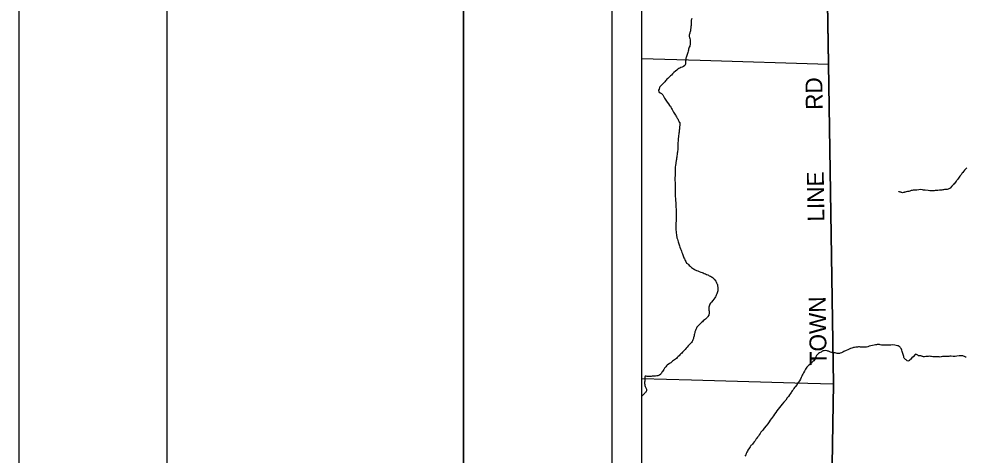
# Model space of a CAD drawing. Extents: x 0 to 34, y 0 to 22.
# Drawn here: x 0 to 3.195, y 15.642 to 17.112 of the extents above; entities that cross this region are included whole.
import ezdxf

# ---------------------------------------------------------------- set-up
doc = ezdxf.new("R2010")
doc.units = 0
for name, color, linetype in [('GM_X_Corporation', 7, 'Continuous'), ('GM_X_Minor_River', 7, 'Continuous'), ('GM_X_Township_Road', 7, 'Continuous'), ('GM_X_Township_Road_Text', 7, 'Continuous'), ('SH_Border', 7, 'Continuous'), ('SH_Cut_Line', 7, 'Continuous'), ('SH_Data', 7, 'Continuous')]:
    doc.layers.add(name, color=color, linetype=linetype)

msp = doc.modelspace()

# ---------------------------------------------------------------- linework, layer by layer
at = {"layer": 'GM_X_Corporation'}
for points in [[(3.1996, 20.2345), (3.1561, 20.2337), (3.1064, 20.2336), (3.0286, 20.2331), (3.0007, 20.2328), (2.9354, 20.2326), (2.8825, 20.2322), (2.8234, 20.2319), (2.7333, 20.2317), (2.6825, 20.2316), (2.6344, 20.2324), (2.5847, 20.2334), (2.535, 20.2346), (2.5164, 20.2351), (2.4604, 20.2364), (2.3921, 20.2383), (2.333, 20.2398), (2.2833, 20.2411), (2.246, 20.2419), (2.187, 20.2434), (2.1124, 20.2453), (2.1, 20.2456), (2.1, 14.1)], [(3.1996, 20.2345), (3.1561, 20.2337), (3.1064, 20.2336), (3.0286, 20.2331), (3.0007, 20.2328), (2.9354, 20.2326), (2.8825, 20.2322), (2.8234, 20.2319), (2.7333, 20.2317), (2.6825, 20.2316), (2.6883, 19.5017), (2.7024, 18.7188), (2.7184, 17.7156), (2.7304, 16.9599), (2.7477, 15.8824), (2.7366, 15.2014)]]:
    msp.add_lwpolyline(points, dxfattribs=at)
msp.add_lwpolyline([(2.1, 20.2456), (2.1, 15.2121), (2.7366, 15.2014), (2.7477, 15.8824), (2.7304, 16.9599), (2.7184, 17.7156), (2.7024, 18.7188), (2.6883, 19.5017), (2.6825, 20.2316), (2.6344, 20.2324), (2.5847, 20.2334), (2.535, 20.2346), (2.5164, 20.2351), (2.4604, 20.2364), (2.3921, 20.2383), (2.333, 20.2398), (2.2833, 20.2411), (2.246, 20.2419), (2.187, 20.2434), (2.1124, 20.2453)], close=True, dxfattribs=at)
at = {"layer": 'GM_X_Minor_River'}
for points in [[(2.2695, 17.1126), (2.2684, 17.1103), (2.268, 17.108), (2.2675, 17.1046), (2.2671, 17.1005), (2.2671, 17.0978), (2.2671, 17.0959), (2.267, 17.0929), (2.267, 17.0894), (2.2666, 17.0864), (2.2665, 17.0841)], [(2.2665, 17.0841), (2.2665, 17.0822), (2.2661, 17.0799), (2.2657, 17.0773), (2.2653, 17.0746), (2.2649, 17.0716), (2.2637, 17.0682), (2.2629, 17.0663), (2.2625, 17.0636), (2.2617, 17.0606), (2.2609, 17.058), (2.2609, 17.0553), (2.2612, 17.0526), (2.2616, 17.0507), (2.2623, 17.0488), (2.2634, 17.0454), (2.2641, 17.0416), (2.2644, 17.034), (2.2644, 17.0313), (2.264, 17.0271), (2.2639, 17.0245), (2.2631, 17.0218), (2.2627, 17.0199), (2.2612, 17.0161), (2.26, 17.0131), (2.2588, 17.0093), (2.258, 17.007), (2.2572, 17.0029), (2.256, 16.9987), (2.2552, 16.9949), (2.254, 16.9915), (2.2532, 16.9885), (2.252, 16.9851), (2.2509, 16.982), (2.2501, 16.9798), (2.2497, 16.9767), (2.2492, 16.9729), (2.2488, 16.9695), (2.2484, 16.9657), (2.2484, 16.9634), (2.2483, 16.9615), (2.2479, 16.9589), (2.2467, 16.9551), (2.2421, 16.9514), (2.2368, 16.9491), (2.233, 16.9477), (2.2295, 16.9462), (2.2261, 16.9447), (2.2226, 16.9425), (2.2196, 16.9391), (2.215, 16.9361), (2.2088, 16.9308), (2.2065, 16.9286), (2.2046, 16.9267), (2.2007, 16.9226), (2.198, 16.9203), (2.1892, 16.9113), (2.1854, 16.9083), (2.1834, 16.9057), (2.1807, 16.9027), (2.1784, 16.8997), (2.1761, 16.8978), (2.1742, 16.8951), (2.1719, 16.8925), (2.1688, 16.8891), (2.1657, 16.8861), (2.163, 16.8842), (2.1615, 16.8824), (2.1607, 16.8805), (2.1595, 16.8755), (2.1579, 16.8718), (2.159, 16.8664), (2.1631, 16.863), (2.1669, 16.8606), (2.1692, 16.8587), (2.1714, 16.8556), (2.1744, 16.851), (2.1778, 16.8449), (2.1822, 16.8384), (2.1863, 16.8315), (2.1908, 16.8254), (2.1946, 16.82), (2.1976, 16.8173), (2.1991, 16.8143), (2.2013, 16.8104), (2.2031, 16.8062), (2.2057, 16.8016), (2.208, 16.7978), (2.2098, 16.7944), (2.2121, 16.7905), (2.2143, 16.7875), (2.2158, 16.7848), (2.218, 16.7813), (2.2203, 16.7771), (2.2221, 16.7745), (2.2236, 16.7718), (2.2259, 16.7672), (2.2273, 16.7641), (2.2288, 16.7622), (2.2291, 16.7538), (2.2287, 16.7481)], [(2.2287, 16.7481), (2.2283, 16.7447), (2.2278, 16.7406), (2.2274, 16.7371), (2.227, 16.7341), (2.2266, 16.7299), (2.2261, 16.7265), (2.2257, 16.7231), (2.2253, 16.7185), (2.2245, 16.714), (2.224, 16.709), (2.2236, 16.7045), (2.2232, 16.6999), (2.2231, 16.6958), (2.2231, 16.692), (2.2226, 16.687), (2.2226, 16.6821), (2.2225, 16.6779), (2.2221, 16.6741), (2.222, 16.6707), (2.2216, 16.6665), (2.2212, 16.6631), (2.2208, 16.6589), (2.2199, 16.6547), (2.2195, 16.6509), (2.2187, 16.6464), (2.2179, 16.6426), (2.2175, 16.6384), (2.2167, 16.6342), (2.2146, 16.6175), (2.2141, 16.6138), (2.2137, 16.6096), (2.2133, 16.6046), (2.2132, 16.5986), (2.2135, 16.5932), (2.2134, 16.5879), (2.2134, 16.5826), (2.2129, 16.5777), (2.2129, 16.5723), (2.2128, 16.567), (2.2131, 16.5605), (2.2134, 16.5533), (2.2134, 16.5488), (2.2137, 16.5446), (2.2136, 16.54), (2.2136, 16.5358), (2.2135, 16.5309), (2.2135, 16.5267), (2.2138, 16.5229), (2.2138, 16.5191), (2.2141, 16.5134), (2.2144, 16.5069), (2.2147, 16.4986), (2.2154, 16.4936), (2.2157, 16.4887), (2.216, 16.4826), (2.2163, 16.4769), (2.2166, 16.4712), (2.2169, 16.4655), (2.2169, 16.4609), (2.2168, 16.456), (2.2167, 16.4514), (2.2167, 16.4468), (2.2166, 16.4415), (2.2166, 16.4351), (2.2165, 16.4297), (2.2161, 16.4248), (2.216, 16.4195), (2.2159, 16.4145), (2.2159, 16.4096), (2.2162, 16.405), (2.2161, 16.4001), (2.2165, 16.3955), (2.2168, 16.3906), (2.2175, 16.3841), (2.2189, 16.3746), (2.2211, 16.3692), (2.2226, 16.3647), (2.2236, 16.3601), (2.228, 16.3475), (2.2295, 16.3425), (2.2317, 16.3372), (2.2336, 16.3322), (2.2351, 16.3292), (2.2361, 16.325), (2.238, 16.3204), (2.2391, 16.317), (2.2406, 16.3131), (2.2417, 16.3101), (2.2431, 16.3066), (2.2446, 16.3032), (2.2457, 16.3005), (2.2468, 16.2979), (2.2491, 16.2948), (2.2521, 16.2891), (2.2558, 16.286), (2.2585, 16.2837), (2.2607, 16.281), (2.2637, 16.2787), (2.2663, 16.2763), (2.269, 16.274)], [(3.1979, 16.6101), (3.1895, 16.6018), (3.186, 16.5977), (3.1837, 16.5947), (3.1821, 16.5928), (3.1802, 16.5898), (3.1783, 16.5875), (3.1767, 16.5852), (3.174, 16.5815), (3.1721, 16.5781), (3.1694, 16.5747), (3.1671, 16.572), (3.1651, 16.5698), (3.1636, 16.5675), (3.1616, 16.5645), (3.1593, 16.5611), (3.1566, 16.5581), (3.1547, 16.5566), (3.152, 16.5536), (3.147, 16.5476), (3.1408, 16.5419), (3.1347, 16.5382), (3.1313, 16.5371), (3.1267, 16.5372), (3.1225, 16.5368), (3.1187, 16.5361), (3.1161, 16.5358), (3.1134, 16.5351), (3.1115, 16.5351), (3.1054, 16.5348), (3.1001, 16.5341), (3.0955, 16.5334), (3.0921, 16.533), (3.0902, 16.533), (3.0871, 16.5323), (3.0833, 16.532), (3.0784, 16.532), (3.0727, 16.5325), (3.0666, 16.5333), (3.0564, 16.5346), (3.0537, 16.5346), (3.0507, 16.535), (3.0484, 16.5358), (3.0427, 16.5366), (3.0351, 16.5356), (3.029, 16.5345), (3.0263, 16.5342), (3.0229, 16.5342), (3.0195, 16.5343), (3.0161, 16.5343), (3.0126, 16.534), (3.0096, 16.5332), (3.0077, 16.5325), (3.005, 16.5318), (3.0019, 16.5307), (2.9978, 16.53), (2.9932, 16.5289), (2.9894, 16.5278), (2.9875, 16.5278), (2.9856, 16.5267), (2.9833, 16.5263), (2.9806, 16.526), (2.9787, 16.5264), (2.9768, 16.5272), (2.9745, 16.528), (2.9727, 16.5284), (2.9708, 16.5288), (2.9681, 16.5296), (2.9681, 16.5296), (2.9681, 16.5299)], [(2.269, 16.274), (2.272, 16.2717), (2.275, 16.2698), (2.2777, 16.2686), (2.2811, 16.2663), (2.2856, 16.2643), (2.2901, 16.2624), (2.295, 16.2604), (2.3, 16.2588), (2.3045, 16.2573), (2.3079, 16.2557), (2.3113, 16.2541), (2.3155, 16.2522), (2.3196, 16.2502), (2.3234, 16.2491), (2.3261, 16.2479), (2.3287, 16.2463), (2.3332, 16.2444), (2.3366, 16.2424), (2.3389, 16.2413), (2.3412, 16.2397), (2.343, 16.237), (2.3453, 16.2347), (2.3505, 16.2282), (2.3513, 16.2263), (2.3528, 16.2225), (2.355, 16.2183), (2.3565, 16.2164), (2.3568, 16.2125), (2.3575, 16.2072), (2.3578, 16.2023), (2.3574, 16.1985), (2.3574, 16.1958), (2.3562, 16.192), (2.3554, 16.1882), (2.3542, 16.1852), (2.3534, 16.1826), (2.3523, 16.1807), (2.3511, 16.1776), (2.3495, 16.175), (2.3472, 16.1716), (2.3441, 16.1675), (2.3403, 16.1629), (2.336, 16.1573), (2.3333, 16.1539), (2.331, 16.1501), (2.329, 16.1471), (2.3282, 16.1437), (2.3274, 16.1399), (2.327, 16.1354), (2.3273, 16.1308), (2.3277, 16.127), (2.328, 16.1236), (2.3284, 16.1217), (2.3267, 16.1137), (2.324, 16.1088), (2.3221, 16.1065), (2.3205, 16.1039), (2.3182, 16.102), (2.3159, 16.0998), (2.3129, 16.0975), (2.3083, 16.0941), (2.3052, 16.0915), (2.3029, 16.0889), (2.3002, 16.0863), (2.2929, 16.0799), (2.2906, 16.0776), (2.2886, 16.0754), (2.2871, 16.0727), (2.2852, 16.0697), (2.2832, 16.0648), (2.2816, 16.0614), (2.2804, 16.0576), (2.2797, 16.0553), (2.2788, 16.0508), (2.278, 16.0474), (2.2772, 16.0436), (2.2764, 16.0405), (2.2757, 16.0379), (2.2749, 16.0345), (2.2741, 16.0322), (2.2733, 16.0299), (2.2721, 16.0273), (2.2705, 16.0243), (2.2686, 16.0216), (2.2667, 16.019), (2.2632, 16.016), (2.2617, 16.0141), (2.2594, 16.0122), (2.2571, 16.0096), (2.2544, 16.0058), (2.2505, 16.0021), (2.2474, 15.9983), (2.2447, 15.9953), (2.2428, 15.9934), (2.2405, 15.9912), (2.2382, 15.9885), (2.2355, 15.9859), (2.2324, 15.9829), (2.2293, 15.9803), (2.2266, 15.9769)], [(2.9777, 15.9957), (2.9762, 16.0007), (2.974, 16.0038), (2.9721, 16.0057), (2.9706, 16.0076), (2.9687, 16.0084), (2.9657, 16.0096), (2.963, 16.0104), (2.9592, 16.0112), (2.9543, 16.0124), (2.9478, 16.0132), (2.9406, 16.0129), (2.9341, 16.0122), (2.9281, 16.0119), (2.9205, 16.0124), (2.9144, 16.0128), (2.9094, 16.0129), (2.9056, 16.0137), (2.9026, 16.0145), (2.9003, 16.0149), (2.8977, 16.0149), (2.8954, 16.0142), (2.8923, 16.0139), (2.8893, 16.0131), (2.8851, 16.012), (2.868, 16.0088), (2.863, 16.007), (2.8584, 16.0059), (2.8542, 16.0052), (2.8485, 16.0053), (2.8428, 16.0057), (2.8383, 16.0061), (2.8356, 16.0062), (2.8337, 16.0062), (2.8318, 16.0062), (2.8288, 16.0059), (2.8261, 16.0055), (2.8231, 16.0056), (2.8189, 16.0049), (2.8151, 16.0045), (2.8128, 16.0038), (2.8093, 16.0027), (2.8055, 16.0012), (2.8005, 15.999), (2.7956, 15.9968), (2.7902, 15.9942), (2.783, 15.9908), (2.7788, 15.9886), (2.7742, 15.9868), (2.7703, 15.9853), (2.7677, 15.9846), (2.7658, 15.9838), (2.7627, 15.9839), (2.7601, 15.9846), (2.7571, 15.9858), (2.7536, 15.9866), (2.7506, 15.9863), (2.7468, 15.9863), (2.7445, 15.9863), (2.7415, 15.9875), (2.7377, 15.9891), (2.7335, 15.991), (2.7305, 15.9922), (2.7286, 15.9926), (2.7267, 15.9934), (2.7218, 15.9946), (2.7165, 15.9935), (2.713, 15.9928), (2.7111, 15.9924), (2.7092, 15.9917), (2.7058, 15.9891), (2.7004, 15.9861), (2.697, 15.9839), (2.6947, 15.9824), (2.6923, 15.9794), (2.6904, 15.9771), (2.6889, 15.9748), (2.6877, 15.973), (2.6865, 15.9699), (2.6857, 15.9665), (2.6834, 15.9631), (2.6811, 15.9597), (2.678, 15.9571), (2.6761, 15.9552), (2.6742, 15.953), (2.6715, 15.9511), (2.6692, 15.9492), (2.6669, 15.9462), (2.6638, 15.944), (2.6603, 15.941), (2.6573, 15.9383), (2.6534, 15.9319), (2.6495, 15.9251), (2.6464, 15.9191), (2.6441, 15.9146), (2.6421, 15.9108), (2.6406, 15.9078), (2.6386, 15.9036), (2.6359, 15.8979), (2.6328, 15.8923), (2.6293, 15.8881)], [(2.2266, 15.9769), (2.2236, 15.9739), (2.2201, 15.9705), (2.2178, 15.9679), (2.2143, 15.9656), (2.2113, 15.9634), (2.2082, 15.9608), (2.2047, 15.9581), (2.2017, 15.9555), (2.1986, 15.9533), (2.1967, 15.9518), (2.1944, 15.9507), (2.1863, 15.9451), (2.184, 15.9424), (2.1817, 15.9398), (2.1798, 15.9375), (2.1779, 15.9353), (2.1763, 15.9326), (2.1748, 15.93), (2.1728, 15.9274), (2.1705, 15.924), (2.1689, 15.9209), (2.167, 15.9183), (2.1659, 15.9164), (2.1647, 15.9141), (2.1608, 15.9108), (2.157, 15.9097), (2.1551, 15.9093), (2.1513, 15.9086), (2.1467, 15.9083), (2.1437, 15.9083), (2.1414, 15.9083), (2.1388, 15.908), (2.1357, 15.908), (2.1327, 15.9073), (2.13, 15.907), (2.1281, 15.9066), (2.1262, 15.907), (2.1232, 15.907), (2.119, 15.9071), (2.1156, 15.9075), (2.1125, 15.9075), (2.1117, 15.9041), (2.1117, 15.9003), (2.1113, 15.8962), (2.1108, 15.8943), (2.1108, 15.8912), (2.1104, 15.8882), (2.1104, 15.8859), (2.1103, 15.8829), (2.1107, 15.8794), (2.1114, 15.8768), (2.1129, 15.8733), (2.114, 15.8703), (2.1155, 15.8668), (2.1169, 15.8638), (2.1173, 15.8588), (2.1157, 15.8566), (2.1142, 15.8543), (2.1126, 15.8524), (2.1107, 15.8502), (2.108, 15.8472), (2.1053, 15.8445), (2.103, 15.8423), (2.1007, 15.84), (2.1, 15.8395)], [(3.1952, 15.9715), (3.1933, 15.9723), (3.1914, 15.9727), (3.1842, 15.9762), (3.1789, 15.9766), (3.1721, 15.976), (3.1641, 15.9749), (3.158, 15.9746), (3.1508, 15.9747), (3.1451, 15.9748), (3.1405, 15.9748), (3.1363, 15.9745), (3.1317, 15.9738), (3.1272, 15.9738), (3.1238, 15.9739), (3.12, 15.9739), (3.1158, 15.9736), (3.1112, 15.9725), (3.107, 15.9722), (3.1036, 15.9726), (3.0971, 15.973), (3.0899, 15.9731), (3.0831, 15.9732), (3.0781, 15.9736), (3.0743, 15.9745), (3.0709, 15.9749), (3.0671, 15.9745), (3.0637, 15.9742), (3.0591, 15.9739), (3.0542, 15.9732), (3.0515, 15.9732), (3.0489, 15.9736), (3.047, 15.9744), (3.0451, 15.9752), (3.042, 15.976), (3.0394, 15.9768), (3.036, 15.9768), (3.0337, 15.9768), (3.0322, 15.9788), (3.028, 15.9811), (3.0246, 15.9823), (3.0227, 15.9808), (3.0162, 15.9729), (3.0123, 15.9695), (3.0081, 15.965), (3.0054, 15.9631), (3.0035, 15.9605), (3.0016, 15.9594), (2.9985, 15.9586), (2.9962, 15.9598), (2.9932, 15.9625), (2.9902, 15.9644), (2.988, 15.9667), (2.9861, 15.9687), (2.985, 15.9713), (2.9846, 15.9744), (2.9839, 15.977), (2.9828, 15.9809), (2.9817, 15.9843), (2.9806, 15.9877), (2.9795, 15.9915), (2.9777, 15.9957)], [(2.6293, 15.8881), (2.6274, 15.8851), (2.625, 15.8802), (2.6188, 15.8719), (2.6165, 15.8693), (2.6138, 15.8659), (2.6115, 15.8621), (2.6084, 15.858), (2.6061, 15.8549), (2.6045, 15.8531), (2.6022, 15.8497), (2.5995, 15.8455), (2.5953, 15.8399), (2.5918, 15.8346), (2.5871, 15.8274), (2.5806, 15.8199), (2.5748, 15.8135), (2.5698, 15.8079), (2.5652, 15.8022), (2.5609, 15.7969), (2.557, 15.7909), (2.5528, 15.7849), (2.5489, 15.7796), (2.5454, 15.7739), (2.542, 15.7702), (2.5393, 15.7664), (2.5369, 15.7638), (2.5342, 15.76), (2.5307, 15.7543), (2.5257, 15.7476), (2.5203, 15.74), (2.5141, 15.7321), (2.5091, 15.7257), (2.5049, 15.7212), (2.5022, 15.719), (2.5002, 15.7152), (2.4971, 15.7103), (2.4941, 15.7061), (2.4917, 15.7024), (2.489, 15.699), (2.4871, 15.6971), (2.4855, 15.6941), (2.4832, 15.6903), (2.4801, 15.6861), (2.477, 15.682), (2.474, 15.679), (2.4713, 15.6756), (2.4693, 15.6737), (2.4678, 15.6718), (2.4662, 15.6696), (2.4643, 15.6666), (2.4589, 15.6583), (2.4573, 15.6552), (2.4558, 15.6522), (2.4534, 15.6477), (2.4515, 15.6428), (2.4491, 15.6379)]]:
    msp.add_lwpolyline(points, dxfattribs=at)
at = {"layer": 'GM_X_Township_Road'}
for points in [[(2.7371, 15.2138), (2.7479, 15.8819), (2.7307, 16.9594), (2.7186, 17.715)], [(2.1, 16.978), (2.2976, 16.9722), (2.7307, 16.9594)], [(2.1, 15.8995), (2.2683, 15.8953), (2.617, 15.8857), (2.7479, 15.8819)]]:
    msp.add_lwpolyline(points, dxfattribs=at)
at = {"layer": 'SH_Border'}
for points in [[(0.5, 21.5), (1.5, 21.5), (1.5, 0.5), (0.5, 0.5)], [(1.5, 21.5), (33.5, 21.5), (33.5, 0.5), (1.5, 0.5)]]:
    msp.add_lwpolyline(points, close=True, dxfattribs=at)
at = {"layer": 'SH_Cut_Line'}
msp.add_lwpolyline([(0, 0), (34, 0), (34, 22), (0, 22)], close=True, dxfattribs=at)
at = {"layer": 'SH_Data'}
for p, q in [((2, 21), (2, 14)), ((2.1, 20.9), (2.1, 14.1))]:
    msp.add_line(p, q, dxfattribs=at)

# ---------------------------------------------------------------- texts
at = {"layer": 'GM_X_Township_Road_Text'}
for s, rotation, p in [('RD', 90.9872, (2.7114, 16.8058)), ('LINE', 90.9041, (2.7172, 16.4292)), ('TOWN', 90.917, (2.7247, 15.945))]:
    msp.add_text(s, height=0.05682, rotation=rotation, dxfattribs=at).set_placement(p)

doc.saveas('drawing.dxf')
